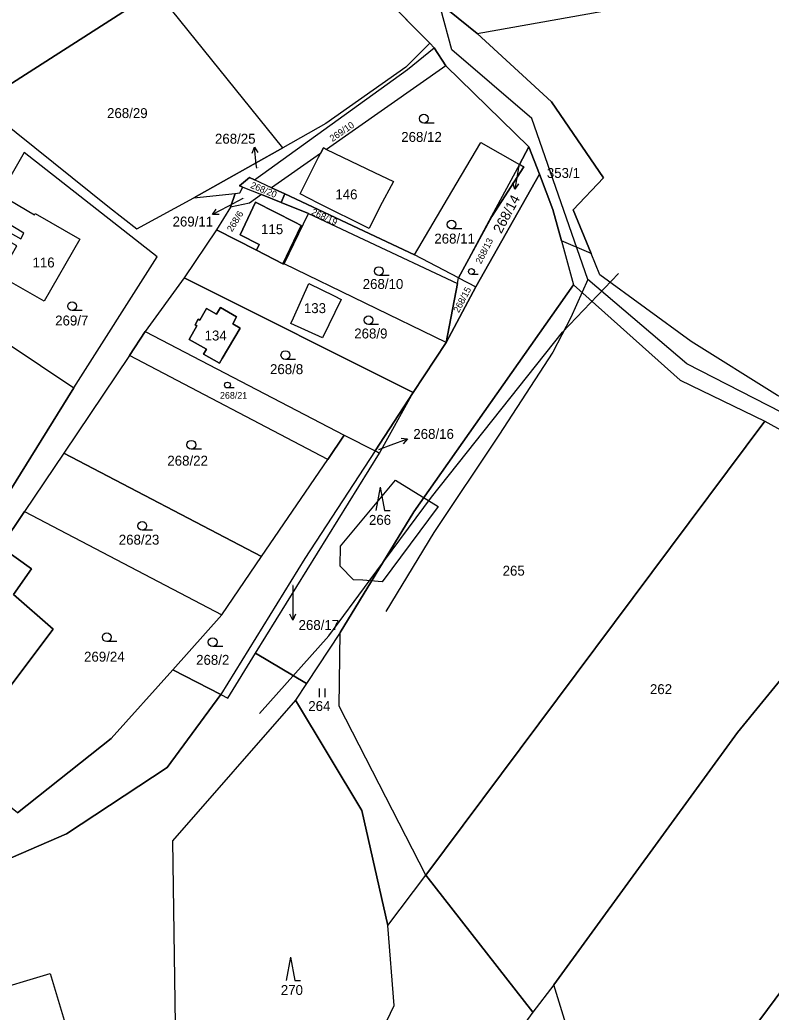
# Model space of a CAD drawing. Extents: x -590606 to -587796, y -1065936 to -1062515.
# Drawn here: x -589044.8 to -588916, y -1064624.7 to -1064454.8 of the extents above; entities that cross this region are included whole.
import ezdxf

# ---------------------------------------------------------------- set-up
doc = ezdxf.new("R2010")
doc.units = 0
for name, color, linetype in [('Cesty', 7, 'Continuous'), ('Parcela nároku', 7, 'Continuous'), ('Parcelní číslo', 7, 'Continuous'), ('Tok', 7, 'Continuous'), ('Vnější obvod_ Studené', 7, 'Continuous'), ('Vrstva 30', 7, 'Continuous')]:
    doc.layers.add(name, color=color, linetype=linetype)

msp = doc.modelspace()

# ---------------------------------------------------------------- linework, layer by layer
at = {"layer": 'Cesty'}
for points in [[(-588898.07, -1064530.25), (-588930.49, -1064513.65), (-588947.47, -1064499.21), (-588952.95, -1064483.46), (-588957.06, -1064471.65), (-588970.78, -1064459.91), (-588972.61, -1064452.95)], [(-588947.47, -1064499.21), (-588950.34, -1064505.72), (-588953.42, -1064511.69), (-588962.68, -1064525.91), (-588973.85, -1064542.55), (-588982.08, -1064556.09)]]:
    msp.add_lwpolyline(points, dxfattribs=at)
at = {"layer": 'Parcela nároku'}
for points in [[(-588702.23, -1064296.8), (-588837.62, -1064350.28), (-588849.45, -1064348.76), (-588873.9, -1064356.01), (-588880.57, -1064392.68), (-588901.98, -1064421.35), (-588933.11, -1064446.5), (-588971.14, -1064453.28), (-588966.43, -1064457.09), (-588932.01, -1064450.94), (-588898.7, -1064423.95), (-588875.06, -1064392.84), (-588869.21, -1064358.66), (-588848.37, -1064352.68), (-588835.76, -1064353.97), (-588702.09, -1064300.85)], [(-588971.14, -1064453.28), (-588966.43, -1064457.09), (-588953.65, -1064468.8), (-588944.74, -1064481.83), (-588949.94, -1064487.27), (-588946.89, -1064494.75), (-588951.96, -1064492.59), (-588953.43, -1064487.26), (-588955.75, -1064481.18), (-588957.54, -1064476.49), (-588971.77, -1064462.64), (-588973.76, -1064459.53), (-588974.53, -1064458.75), (-588991.04, -1064442.06)], [(-588733.73, -1064598.99), (-588751.39, -1064586.78), (-588767.59, -1064570.33), (-588781, -1064558.75), (-588797.78, -1064549.89), (-588810.19, -1064544.34), (-588833.56, -1064539.94), (-588851.76, -1064537.38), (-588883.06, -1064532.07), (-588898.92, -1064527.72), (-588914.98, -1064519.09), (-588929.76, -1064509.87), (-588945.38, -1064498.45), (-588946.89, -1064494.75), (-588949.94, -1064487.27), (-588944.74, -1064481.83), (-588953.65, -1064468.8), (-588966.43, -1064457.09), (-588932.01, -1064450.94)], [(-589048.65, -1064471.48), (-589029.39, -1064486.89), (-589024.72, -1064490.53), (-589014.96, -1064485.26), (-589007.88, -1064484.47), (-589008.65, -1064486.85), (-589011.08, -1064490.71), (-589016.6, -1064498.93), (-589023.3, -1064508.11), (-589026, -1064512.24), (-589037.23, -1064528.94), (-589043.98, -1064538.95), (-589048.04, -1064545)], [(-589051.04, -1064542.74), (-589035.51, -1064517.76), (-589021.25, -1064495.37), (-589044.04, -1064477.46), (-589048.18, -1064484.68)], [(-588914.98, -1064519.09), (-588929.76, -1064509.87), (-588945.38, -1064498.45), (-588946.89, -1064494.75), (-588951.96, -1064492.59), (-588949.9, -1064500.12), (-588931.63, -1064516.46), (-588917.11, -1064523.51), (-588902.66, -1064531.5)], [(-589048.04, -1064545), (-589042.74, -1064548.76), (-589045.87, -1064553.17), (-589039.04, -1064559.11), (-589056.12, -1064581.74)], [(-589179.39, -1064625.08), (-589169.88, -1064604.99), (-589157.66, -1064613.8), (-589140.42, -1064589.07), (-589133.86, -1064593.72), (-589126.67, -1064616.12), (-589063.15, -1064605.55), (-589036.79, -1064594.17), (-589019.52, -1064582.82), (-589010.33, -1064570.28), (-589009.13, -1064570.9), (-589004.37, -1064563.21), (-588995.65, -1064568.41), (-588997.54, -1064571.27), (-589018.59, -1064595.36), (-589018.06, -1064634.7)], [(-589045.18, -1064590.56), (-589029.13, -1064577.85), (-589018.54, -1064566.04), (-589010.33, -1064570.28), (-589019.52, -1064582.82), (-589036.79, -1064594.17), (-589063.15, -1064605.55)]]:
    msp.add_lwpolyline(points, dxfattribs=at)
for points in [[(-589054.48, -1064435.41), (-589077.97, -1064446.72), (-589067.07, -1064453.97), (-589061.52, -1064458.43), (-589057.13, -1064462.5), (-589051.17, -1064468.81), (-589021.42, -1064449.73), (-589042.45, -1064423.68), (-589046.93, -1064428.46)], [(-588991.04, -1064442.06), (-588974.53, -1064458.75), (-588978.65, -1064462.87), (-588992.34, -1064472.52), (-588999.69, -1064476.66), (-589021.42, -1064449.73), (-588997.15, -1064434.16)], [(-589021.42, -1064449.73), (-589051.17, -1064468.81), (-589048.65, -1064471.48), (-589029.39, -1064486.89), (-589024.72, -1064490.53), (-589014.96, -1064485.26), (-588999.69, -1064476.66)], [(-588992.34, -1064472.52), (-588999.69, -1064476.66), (-589014.96, -1064485.26), (-589007.88, -1064484.47), (-589007.09, -1064484.38), (-589006.57, -1064483.39), (-589007.1, -1064483.18), (-589005.4, -1064481.73), (-589004.54, -1064482.14), (-588978.36, -1064463.25), (-588973.76, -1064459.53), (-588974.53, -1064458.75), (-588978.65, -1064462.87)], [(-589001.62, -1064483.51), (-589004.54, -1064482.14), (-588978.36, -1064463.25), (-588973.76, -1064459.53), (-588971.77, -1064462.64), (-588992.22, -1064476.94), (-588992.74, -1064476.69), (-588993.26, -1064477.66)], [(-588983.08, -1064486.78), (-588984.92, -1064490.51), (-588993.65, -1064486.13), (-588996.74, -1064484.54), (-588993.58, -1064478.27), (-588993.26, -1064477.66), (-589001.62, -1064483.51), (-588999.38, -1064484.56), (-588977.17, -1064495.02), (-588970.76, -1064484.17), (-588965.8, -1064475.79), (-588959.18, -1064479.53), (-588957.54, -1064476.49), (-588971.77, -1064462.64), (-588992.22, -1064476.94), (-588984, -1064480.91), (-588980.77, -1064482.46)], [(-588996.74, -1064484.54), (-588993.58, -1064478.27), (-588993.26, -1064477.66), (-588992.74, -1064476.69), (-588992.22, -1064476.94), (-588984, -1064480.91), (-588980.77, -1064482.46), (-588983.08, -1064486.78), (-588984.92, -1064490.51), (-588993.65, -1064486.13)], [(-588977.17, -1064495.02), (-588970.76, -1064484.17), (-588965.8, -1064475.79), (-588959.18, -1064479.53), (-588963.95, -1064488.4), (-588969.62, -1064498.94)], [(-588957.54, -1064476.49), (-588959.18, -1064479.53), (-588958.43, -1064479.95), (-588963.91, -1064488.43), (-588969.62, -1064498.94), (-588966.63, -1064500.49), (-588955.75, -1064481.18)], [(-589040.6, -1064502.91), (-589048.23, -1064498.62), (-589045.3, -1064493.48), (-589047.13, -1064492.43), (-589046.44, -1064491.21), (-589044.61, -1064492.26), (-589044.06, -1064491.3), (-589049.94, -1064487.74), (-589058.39, -1064502.47), (-589035.51, -1064517.76), (-589021.25, -1064495.37), (-589044.04, -1064477.46), (-589048.18, -1064484.68), (-589042.27, -1064488.16), (-589042.15, -1064487.94), (-589034.46, -1064492.34)], [(-588959.18, -1064479.53), (-588963.95, -1064488.4), (-588969.62, -1064498.94), (-588963.91, -1064488.43), (-588958.43, -1064479.95)], [(-589005.4, -1064481.73), (-589007.1, -1064483.18), (-589006.57, -1064483.39), (-589003.35, -1064484.69), (-588999.98, -1064486.05), (-588999.38, -1064484.56), (-589001.62, -1064483.51), (-589004.54, -1064482.14)], [(-588971.74, -1064510.01), (-588966.63, -1064500.49), (-588955.75, -1064481.18), (-588953.43, -1064487.26), (-588951.96, -1064492.59), (-588949.9, -1064500.12), (-588977.26, -1064538.99), (-588989.87, -1064559.66), (-588995.65, -1064568.41), (-589004.37, -1064563.21), (-588983.17, -1064528.97), (-588977.38, -1064518.6)], [(-589007.88, -1064484.47), (-589007.09, -1064484.38), (-589006.57, -1064483.39), (-589003.35, -1064484.69), (-589005.44, -1064486.13), (-589008.65, -1064486.85)], [(-589046.44, -1064491.21), (-589044.61, -1064492.26), (-589044.06, -1064491.3), (-589049.94, -1064487.74), (-589048.18, -1064484.68), (-589042.27, -1064488.16), (-589042.15, -1064487.94), (-589034.46, -1064492.34), (-589040.6, -1064502.91), (-589048.23, -1064498.62), (-589045.3, -1064493.48), (-589047.13, -1064492.43)], [(-588999.98, -1064486.05), (-589003.35, -1064484.69), (-589005.44, -1064486.13), (-589008.65, -1064486.85), (-589011.08, -1064490.71), (-589004.24, -1064494.18), (-589003.77, -1064493.25), (-589007, -1064491.59), (-589004.38, -1064485.99), (-588997.66, -1064489.41), (-588996.54, -1064489.98), (-588999.73, -1064496.57), (-588999.5, -1064496.56), (-588995.28, -1064487.94)], [(-588969.62, -1064498.94), (-588977.17, -1064495.02), (-588999.38, -1064484.56), (-588999.98, -1064486.05), (-588995.28, -1064487.94), (-588985.84, -1064492.37), (-588969.8, -1064499.91)], [(-589004.38, -1064485.99), (-589007, -1064491.59), (-589003.77, -1064493.25), (-589004.24, -1064494.18), (-588999.73, -1064496.57), (-588996.54, -1064489.98), (-588997.66, -1064489.41)], [(-588985.84, -1064492.37), (-588969.8, -1064499.91), (-588971.74, -1064510.01), (-588999.5, -1064496.56), (-588995.28, -1064487.94)], [(-588999.73, -1064496.57), (-589004.24, -1064494.18), (-589011.08, -1064490.71), (-589016.6, -1064498.93), (-588977.38, -1064518.6), (-588971.74, -1064510.01), (-588999.5, -1064496.56)], [(-588977.38, -1064518.6), (-589016.6, -1064498.93), (-589023.3, -1064508.11), (-588989.18, -1064525.87), (-588983.9, -1064528.59)], [(-588969.8, -1064499.91), (-588969.62, -1064498.94), (-588966.63, -1064500.49), (-588971.74, -1064510.01)], [(-588990.89, -1064502.05), (-588989.7, -1064502.63), (-588992.91, -1064509.24), (-588998.35, -1064506.78), (-588997.89, -1064505.81), (-588995.23, -1064499.92)], [(-588992.91, -1064509.24), (-588998.35, -1064506.78), (-588997.89, -1064505.81), (-588995.23, -1064499.92), (-588990.89, -1064502.05), (-588989.7, -1064502.63)], [(-588989.87, -1064559.66), (-588977.26, -1064538.99), (-588949.9, -1064500.12), (-588931.63, -1064516.46), (-588917.11, -1064523.51), (-588975.18, -1064601.25), (-588990.05, -1064572.27)], [(-589073.49, -1064528.42), (-589065, -1064514.23), (-589059.07, -1064516.43), (-589059.42, -1064516.96), (-589052.04, -1064521.86), (-589051.51, -1064521.07), (-589050.55, -1064521.72), (-589046.57, -1064515.81), (-589047.52, -1064515.17), (-589046.98, -1064514.36), (-589054.41, -1064509.35), (-589056.13, -1064508.19), (-589058.63, -1064512.18), (-589062.32, -1064509.54), (-589058.39, -1064502.47), (-589035.51, -1064517.76), (-589051.04, -1064542.74), (-589072.17, -1064529.26)], [(-589011.08, -1064505.19), (-589012.8, -1064504.2), (-589013.92, -1064506.2), (-589014.19, -1064506.04), (-589014.73, -1064507), (-589014.45, -1064507.16), (-589015.77, -1064509.52), (-589012.81, -1064511.18), (-589013.28, -1064512.01), (-589010.54, -1064513.54), (-589010.07, -1064512.74), (-589007, -1064507.54), (-589008.29, -1064506.8), (-589007.62, -1064505.64), (-589010.41, -1064504.03)], [(-589012.81, -1064511.18), (-589015.77, -1064509.52), (-589014.45, -1064507.16), (-589014.73, -1064507), (-589014.19, -1064506.04), (-589013.92, -1064506.2), (-589012.8, -1064504.2), (-589011.08, -1064505.19), (-589010.41, -1064504.03), (-589007.62, -1064505.64), (-589008.29, -1064506.8), (-589007, -1064507.54), (-589010.07, -1064512.74), (-589010.54, -1064513.54), (-589013.28, -1064512.01)], [(-589026, -1064512.24), (-589023.3, -1064508.11), (-588989.18, -1064525.87), (-588992.02, -1064530.04)], [(-588992.02, -1064530.04), (-589026, -1064512.24), (-589037.23, -1064528.94), (-589003.34, -1064546.68)], [(-588977.38, -1064518.6), (-588983.9, -1064528.59), (-588983.17, -1064528.97)], [(-588917.11, -1064523.51), (-588902.66, -1064531.5), (-588889.35, -1064537.12), (-588921.82, -1064576.81), (-588953.26, -1064619.99), (-588956.87, -1064624.68), (-588975.18, -1064601.25)], [(-588989.18, -1064525.87), (-588983.9, -1064528.59), (-588995.93, -1064547.01), (-589010.33, -1064570.28), (-589018.54, -1064566.04), (-589010.14, -1064556.67), (-589003.34, -1064546.68), (-588992.02, -1064530.04)], [(-589037.23, -1064528.94), (-589043.98, -1064538.95), (-589010.14, -1064556.67), (-589003.34, -1064546.68)], [(-588983.9, -1064528.59), (-588995.93, -1064547.01), (-589010.33, -1064570.28), (-589009.13, -1064570.9), (-589004.37, -1064563.21), (-588983.17, -1064528.97)], [(-588921.82, -1064576.81), (-588889.35, -1064537.12), (-588851.4, -1064545.12), (-588898.31, -1064599.49), (-588941.62, -1064657.84), (-588953.26, -1064619.99)], [(-589048.04, -1064545), (-589043.98, -1064538.95), (-589010.14, -1064556.67), (-589018.54, -1064566.04), (-589029.13, -1064577.85), (-589045.18, -1064590.56), (-589056.12, -1064581.74), (-589039.04, -1064559.11), (-589045.87, -1064553.17), (-589042.74, -1064548.76)], [(-588851.4, -1064545.12), (-588839.04, -1064546.13), (-588805.58, -1064554.11), (-588792.71, -1064559.39), (-588782.54, -1064564.66), (-588772.3, -1064573.34), (-588757.48, -1064588.92), (-588770.58, -1064594.99), (-588786.57, -1064605.7), (-588800.43, -1064621.56), (-588815.43, -1064642.06), (-588829.52, -1064669.09), (-588842.19, -1064696.66), (-588844.89, -1064709.35), (-588941.62, -1064657.84), (-588898.31, -1064599.49)], [(-588995.65, -1064568.41), (-588997.54, -1064571.27), (-588986.18, -1064590.18), (-588981.74, -1064609.85), (-588975.18, -1064601.25), (-588990.05, -1064572.27), (-588989.87, -1064559.66)], [(-588997.54, -1064571.27), (-589018.59, -1064595.36), (-589018.06, -1064634.7), (-589016.44, -1064645.68), (-588985.3, -1064643.81), (-588985.82, -1064634.41), (-588980.63, -1064623.57), (-588981.74, -1064609.85), (-588986.18, -1064590.18)], [(-588985.82, -1064634.41), (-588980.63, -1064623.57), (-588981.74, -1064609.85), (-588975.18, -1064601.25), (-588956.87, -1064624.68), (-588981.77, -1064658.84), (-588985.3, -1064643.81)], [(-588941.62, -1064657.84), (-588953.26, -1064619.99), (-588956.87, -1064624.68), (-588981.77, -1064658.84), (-588980.15, -1064668.39), (-588974.19, -1064693.78), (-588958.49, -1064677.96), (-588952.5, -1064671.53)]]:
    msp.add_lwpolyline(points, close=True, dxfattribs=at)
at = {"layer": 'Parcelní číslo'}
for p, q in [((-589004.25, -1064479.54), (-589004.57, -1064476.56)), ((-589004.18, -1064480.15), (-589004.25, -1064479.54)), ((-588959.32, -1064480), (-588959.46, -1064480.79)), ((-588959.46, -1064480.79), (-588959.98, -1064483.74)), ((-589006.56, -1064485.38), (-589009.1, -1064486.71)), ((-589009.1, -1064486.71), (-589011.76, -1064488.1)), ((-588981.16, -1064527.56), (-588978.35, -1064526.52)), ((-588983.23, -1064528.32), (-588981.16, -1064527.56)), ((-588998.01, -1064551.61), (-588998.01, -1064554.54)), ((-588998.01, -1064554.54), (-588998.01, -1064557.54))]:
    msp.add_line(p, q, dxfattribs=at)
for points in [[(-589004.96, -1064477.6), (-589004.57, -1064476.56), (-589003.97, -1064477.5)], [(-588959.32, -1064482.85), (-588959.98, -1064483.74), (-588960.3, -1064482.67)], [(-589010.64, -1064488.08), (-589011.76, -1064488.1), (-589011.1, -1064487.2)], [(-588979.46, -1064526.4), (-588978.35, -1064526.52), (-588979.11, -1064527.34)], [(-588997.51, -1064556.54), (-588998.01, -1064557.54), (-588998.51, -1064556.54)]]:
    msp.add_lwpolyline(points, dxfattribs=at)
at = {"layer": 'Tok'}
msp.add_lwpolyline([(-589003.73, -1064573.54), (-588991.82, -1064560.25), (-588984.9, -1064550.9), (-588974.24, -1064536.5), (-588951.82, -1064508.23), (-588942.19, -1064498.19)], dxfattribs=at)
for points in [[(-588980.4, -1064533.57), (-588973.12, -1064538.08), (-588982.7, -1064550.98), (-588986.02, -1064550.74), (-588987.57, -1064550.63), (-588989.86, -1064548.29), (-588989.82, -1064544.89)], [(-589050.66, -1064621.38), (-589039.58, -1064618.05), (-589032.2, -1064642.61), (-589042.85, -1064645.81)]]:
    msp.add_lwpolyline(points, close=True, dxfattribs=at)
at = {"layer": 'Vnější obvod_ Studené'}
for p, q in [((-588991.04, -1064442.06), (-588974.53, -1064458.75)), ((-588966.43, -1064457.09), (-588971.14, -1064453.28)), ((-588953.65, -1064468.8), (-588966.43, -1064457.09)), ((-588974.53, -1064458.75), (-588973.76, -1064459.53)), ((-588973.76, -1064459.53), (-588971.77, -1064462.64)), ((-588971.77, -1064462.64), (-588957.54, -1064476.49)), ((-588944.74, -1064481.83), (-588953.65, -1064468.8)), ((-588957.54, -1064476.49), (-588955.75, -1064481.18)), ((-588955.75, -1064481.18), (-588966.63, -1064500.49)), ((-588949.94, -1064487.27), (-588944.74, -1064481.83)), ((-588946.89, -1064494.75), (-588949.94, -1064487.27)), ((-588945.38, -1064498.45), (-588946.89, -1064494.75)), ((-588929.76, -1064509.87), (-588945.38, -1064498.45)), ((-588966.63, -1064500.49), (-588971.74, -1064510.01)), ((-588971.74, -1064510.01), (-588977.38, -1064518.6)), ((-588914.98, -1064519.09), (-588929.76, -1064509.87)), ((-588977.38, -1064518.6), (-588983.9, -1064528.59)), ((-588983.9, -1064528.59), (-588995.93, -1064547.01)), ((-588995.93, -1064547.01), (-589010.33, -1064570.28)), ((-589010.33, -1064570.28), (-589019.52, -1064582.82)), ((-589019.52, -1064582.82), (-589036.79, -1064594.17)), ((-589036.79, -1064594.17), (-589063.15, -1064605.55))]:
    msp.add_line(p, q, dxfattribs=at)
at = {"layer": 'Vrstva 30'}
for p, q in [((-588973.8, -1064472.43), (-588975.55, -1064472.43)), ((-588969.05, -1064490.56), (-588970.8, -1064490.56)), ((-588981.5, -1064498.53), (-588983.25, -1064498.53)), ((-588966.22, -1064498.37), (-588967.39, -1064498.37)), ((-589034.06, -1064504.53), (-589035.81, -1064504.53)), ((-588983.29, -1064506.93), (-588985.04, -1064506.93)), ((-588997.52, -1064512.92), (-588999.27, -1064512.92)), ((-589008.02, -1064517.8), (-589009.19, -1064517.8)), ((-589013.63, -1064528.27), (-589015.38, -1064528.27)), ((-588983.04, -1064534.78), (-588983.78, -1064538.78)), ((-588983.04, -1064534.78), (-588982.31, -1064538.78)), ((-588982.31, -1064538.78), (-588981.31, -1064538.78)), ((-589022.04, -1064542.16), (-589023.79, -1064542.16)), ((-589028.12, -1064561.24), (-589029.87, -1064561.24)), ((-589009.97, -1064562.07), (-589011.72, -1064562.07)), ((-588993.5, -1064569.24), (-588993.5, -1064570.74)), ((-588992.47, -1064570.74), (-588992.47, -1064569.24)), ((-588998.38, -1064615.26), (-588999.11, -1064619.26)), ((-588998.38, -1064615.26), (-588997.65, -1064619.26)), ((-588997.65, -1064619.26), (-588996.65, -1064619.26))]:
    msp.add_line(p, q, dxfattribs=at)
for centre, radius in [((-588975.55, -1064471.68), 0.75), ((-588970.8, -1064489.81), 0.75), ((-588983.25, -1064497.78), 0.75), ((-588967.39, -1064497.87), 0.503), ((-589035.81, -1064503.78), 0.75), ((-588985.04, -1064506.18), 0.75), ((-588999.27, -1064512.17), 0.75), ((-589009.19, -1064517.3), 0.503), ((-589015.38, -1064527.52), 0.75), ((-589023.79, -1064541.41), 0.75), ((-589029.87, -1064560.49), 0.75), ((-589011.72, -1064561.32), 0.75)]:
    msp.add_circle(centre, radius, dxfattribs=at)

# ---------------------------------------------------------------- texts
at = {"layer": 'Parcela nároku'}
for s, height, p in [('268/29', 1.7, (-589029.82, -1064471.58)), ('268/12', 1.7, (-588979.42, -1064475.66)), ('268/25', 0.1, (-589004.18, -1064480.15)), ('353/1', 1.7, (-588954.48, -1064481.83)), ('146', 1.7, (-588990.71, -1064485.5)), ('269/11', 0.1, (-589006.56, -1064485.38)), ('115', 1.7, (-589003.43, -1064491.46)), ('268/11', 1.7, (-588973.75, -1064493.07)), ('116', 1.7, (-589042.59, -1064497.16)), ('268/10', 1.7, (-588986.02, -1064500.84)), ('133', 1.7, (-588996.1, -1064504.98)), ('269/7', 1.7, (-589038.71, -1064507.1)), ('134', 1.7, (-589013.11, -1064509.67)), ('268/9', 1.7, (-588987.47, -1064509.32)), ('268/8', 1.7, (-589001.9, -1064515.43)), ('268/21', 1.14, (-589010.47, -1064519.64)), ('268/16', 0.1, (-588983.43, -1064528.32)), ('268/22', 1.7, (-589019.49, -1064531.1)), ('266', 1.7, (-588984.95, -1064541.24)), ('268/23', 1.7, (-589027.81, -1064544.63)), ('265', 1.7, (-588962.05, -1064549.94)), ('268/17', 0.1, (-588998.21, -1064551.61)), ('269/24', 1.7, (-589033.76, -1064564.67)), ('268/2', 1.7, (-589014.56, -1064565.21)), ('262', 1.7, (-588936.81, -1064570.23)), ('264', 1.7, (-588995.34, -1064573.12)), ('270', 1.7, (-589000.05, -1064621.75))]:
    msp.add_text(s, height=height, dxfattribs=at).set_placement(p)
for s, height, rotation, p in [('269/10', 1.14, 34.36, (-588991.2, -1064475.68)), ('268/14', 0.1, 57.7891, (-588959.21, -1064480.09)), ('268/20', 1.14, 337.6199, (-589005.34, -1064483.5)), ('268/6', 1.14, 58.1282, (-589008.41, -1064491.17)), ('268/19', 1.14, 335.2249, (-588994.93, -1064488.05)), ('268/13', 1.14, 63.0241, (-588965.75, -1064496.67)), ('268/15', 1.14, 62.1887, (-588969.56, -1064505.01))]:
    msp.add_text(s, height=height, rotation=rotation, dxfattribs=at).set_placement(p)
at = {"layer": 'Parcelní číslo'}
for s, p in [('268/25', (-589011.33, -1064475.97)), ('269/11', (-589018.6, -1064490.15)), ('268/16', (-588977.35, -1064526.52)), ('268/17', (-588997.01, -1064559.24))]:
    msp.add_text(s, height=1.7, dxfattribs=at).set_placement(p)
msp.add_text('268/14', height=1.7, rotation=61.9551, dxfattribs=at).set_placement((-588962.28, -1064491.47))

doc.saveas('drawing.dxf')
